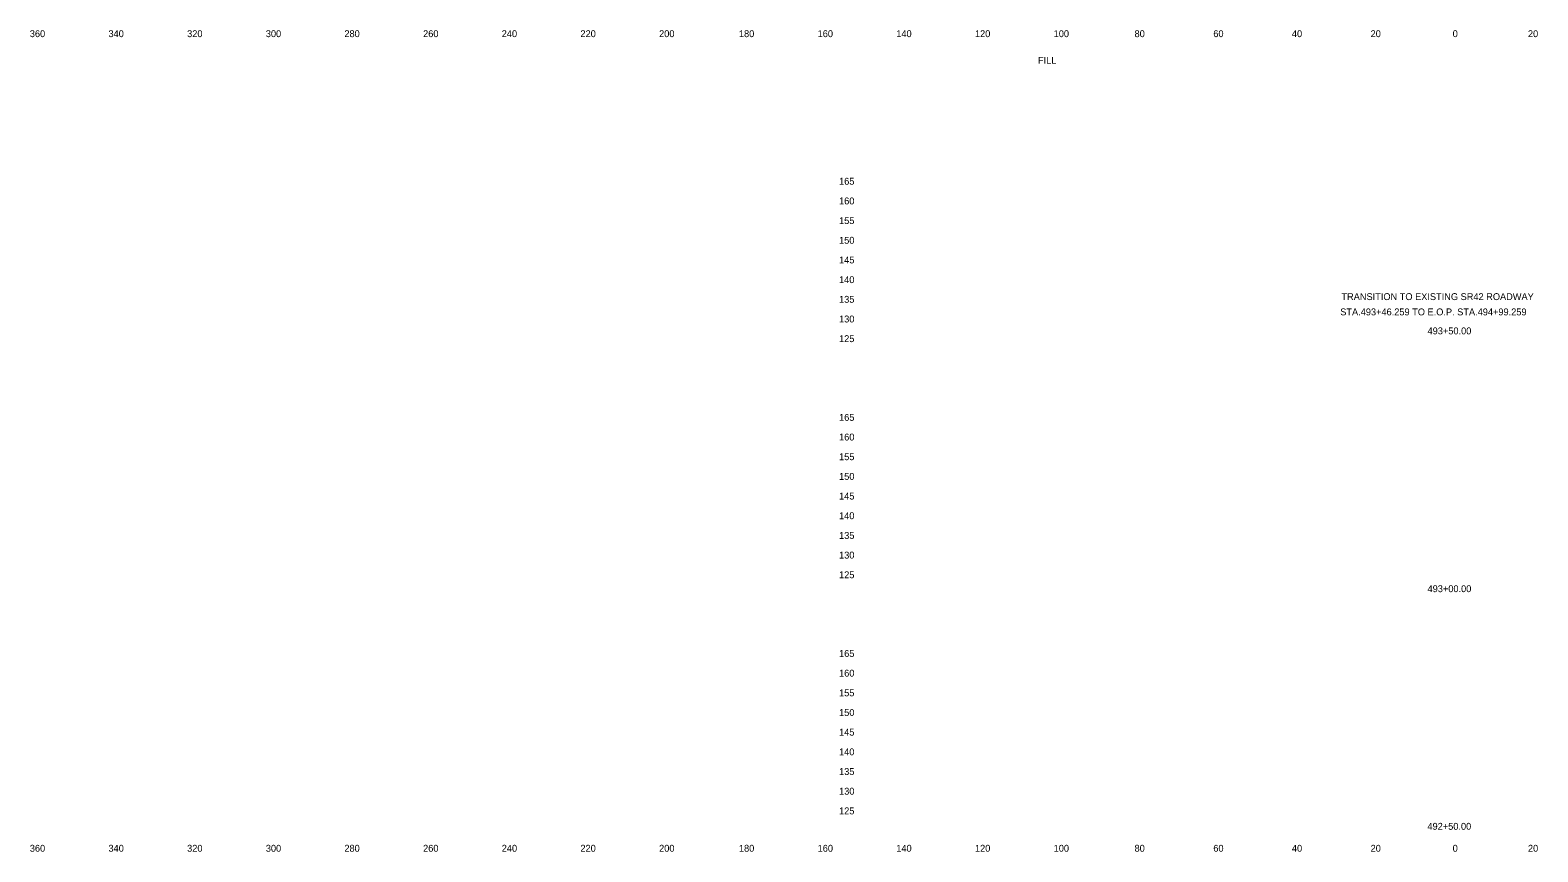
# Model space of a CAD drawing. Extents: x 21281 to 22024, y 6472 to 6918.
# Drawn here: x 21280.5 to 21663.8, y 6475.3 to 6684.1 of the extents above; entities that cross this region are included whole.
import ezdxf

# ---------------------------------------------------------------- set-up
doc = ezdxf.new("R2010")
doc.units = 0
doc.layers.add('XS_SHEET_EW_TX_VOLUME', color=7, linetype='Continuous')
doc.layers.add('XS_SHEET_LABELS_OFFSET', color=7, linetype='Continuous')

msp = doc.modelspace()

# ---------------------------------------------------------------- texts
at = {"layer": 'XS_SHEET_EW_TX_VOLUME'}
for s, p in [('  160  ', (21479.4, 6682.34)), ('  140  ', (21499.39, 6682.34)), ('  120  ', (21519.39, 6682.34)), ('  100  ', (21539.39, 6682.34)), ('  80  ', (21559.95, 6682.34)), ('  60  ', (21579.97, 6682.34)), ('  40  ', (21599.95, 6682.34)), ('  20  ', (21619.95, 6682.34)), ('  0  ', (21640.81, 6682.34)), ('  0  ', (21640.81, 6682.34)), ('  20  ', (21659.95, 6682.34)), ('FILL', (21536.71, 6675.57)), ('  165  ', (21484.84, 6644.84)), ('  160  ', (21484.84, 6639.84)), ('  155  ', (21484.84, 6634.84)), ('  150  ', (21484.84, 6629.84)), ('  145  ', (21484.84, 6624.84)), ('  140  ', (21484.84, 6619.84)), ('  135  ', (21484.84, 6614.84)), ('TRANSITION TO EXISTING SR42 ROADWAY', (21613.84, 6615.52)), ('  130  ', (21484.84, 6609.84)), ('STA.493+46.259 TO E.O.P. STA.494+99.259', (21613.54, 6611.64)), ('  493+50.00  ', (21634.43, 6606.82)), ('  125  ', (21484.84, 6604.84)), ('  165  ', (21484.84, 6584.84)), ('  160  ', (21484.84, 6579.84)), ('  155  ', (21484.84, 6574.84)), ('  150  ', (21484.84, 6569.84)), ('  145  ', (21484.84, 6564.84)), ('  140  ', (21484.84, 6559.84)), ('  135  ', (21484.84, 6554.84)), ('  130  ', (21484.84, 6549.84)), ('  125  ', (21484.84, 6544.84)), ('  493+00.00  ', (21634.43, 6541.3)), ('  165  ', (21484.84, 6524.84)), ('  160  ', (21484.84, 6519.84)), ('  155  ', (21484.84, 6514.84)), ('  150  ', (21484.84, 6509.84)), ('  145  ', (21484.84, 6504.84)), ('  140  ', (21484.84, 6499.84)), ('  135  ', (21484.84, 6494.84)), ('  130  ', (21484.84, 6489.84)), ('  125  ', (21484.84, 6484.84)), ('  492+50.00  ', (21634.4, 6480.92)), ('  180  ', (21459.39, 6475.34)), ('  160  ', (21479.4, 6475.34)), ('  140  ', (21499.39, 6475.34)), ('  120  ', (21519.39, 6475.34)), ('  100  ', (21539.39, 6475.34)), ('  80  ', (21559.95, 6475.34)), ('  60  ', (21579.97, 6475.34)), ('  40  ', (21599.95, 6475.34)), ('  20  ', (21619.95, 6475.34)), ('  0  ', (21640.81, 6475.34)), ('  0  ', (21640.81, 6475.34)), ('  20  ', (21659.95, 6475.34))]:
    msp.add_text(s, height=1.75, dxfattribs=at).set_placement(p)
at = {"layer": 'XS_SHEET_LABELS_OFFSET'}
for s, p in [('  360  ', (21279.14, 6682.34)), ('  340  ', (21299.13, 6682.34)), ('  320  ', (21319.13, 6682.34)), ('  300  ', (21339.13, 6682.34)), ('  280  ', (21359.1, 6682.34)), ('  260  ', (21379.11, 6682.34)), ('  240  ', (21399.1, 6682.34)), ('  220  ', (21419.1, 6682.34)), ('  200  ', (21439.1, 6682.34)), ('  180  ', (21459.39, 6682.34)), ('  360  ', (21279.14, 6475.34)), ('  340  ', (21299.13, 6475.34)), ('  320  ', (21319.13, 6475.34)), ('  300  ', (21339.13, 6475.34)), ('  280  ', (21359.1, 6475.34)), ('  260  ', (21379.11, 6475.34)), ('  240  ', (21399.1, 6475.34)), ('  220  ', (21419.1, 6475.34)), ('  200  ', (21439.1, 6475.34))]:
    msp.add_text(s, height=1.75, dxfattribs=at).set_placement(p)

doc.saveas('drawing.dxf')
